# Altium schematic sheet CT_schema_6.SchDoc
size 405 x 220 mm
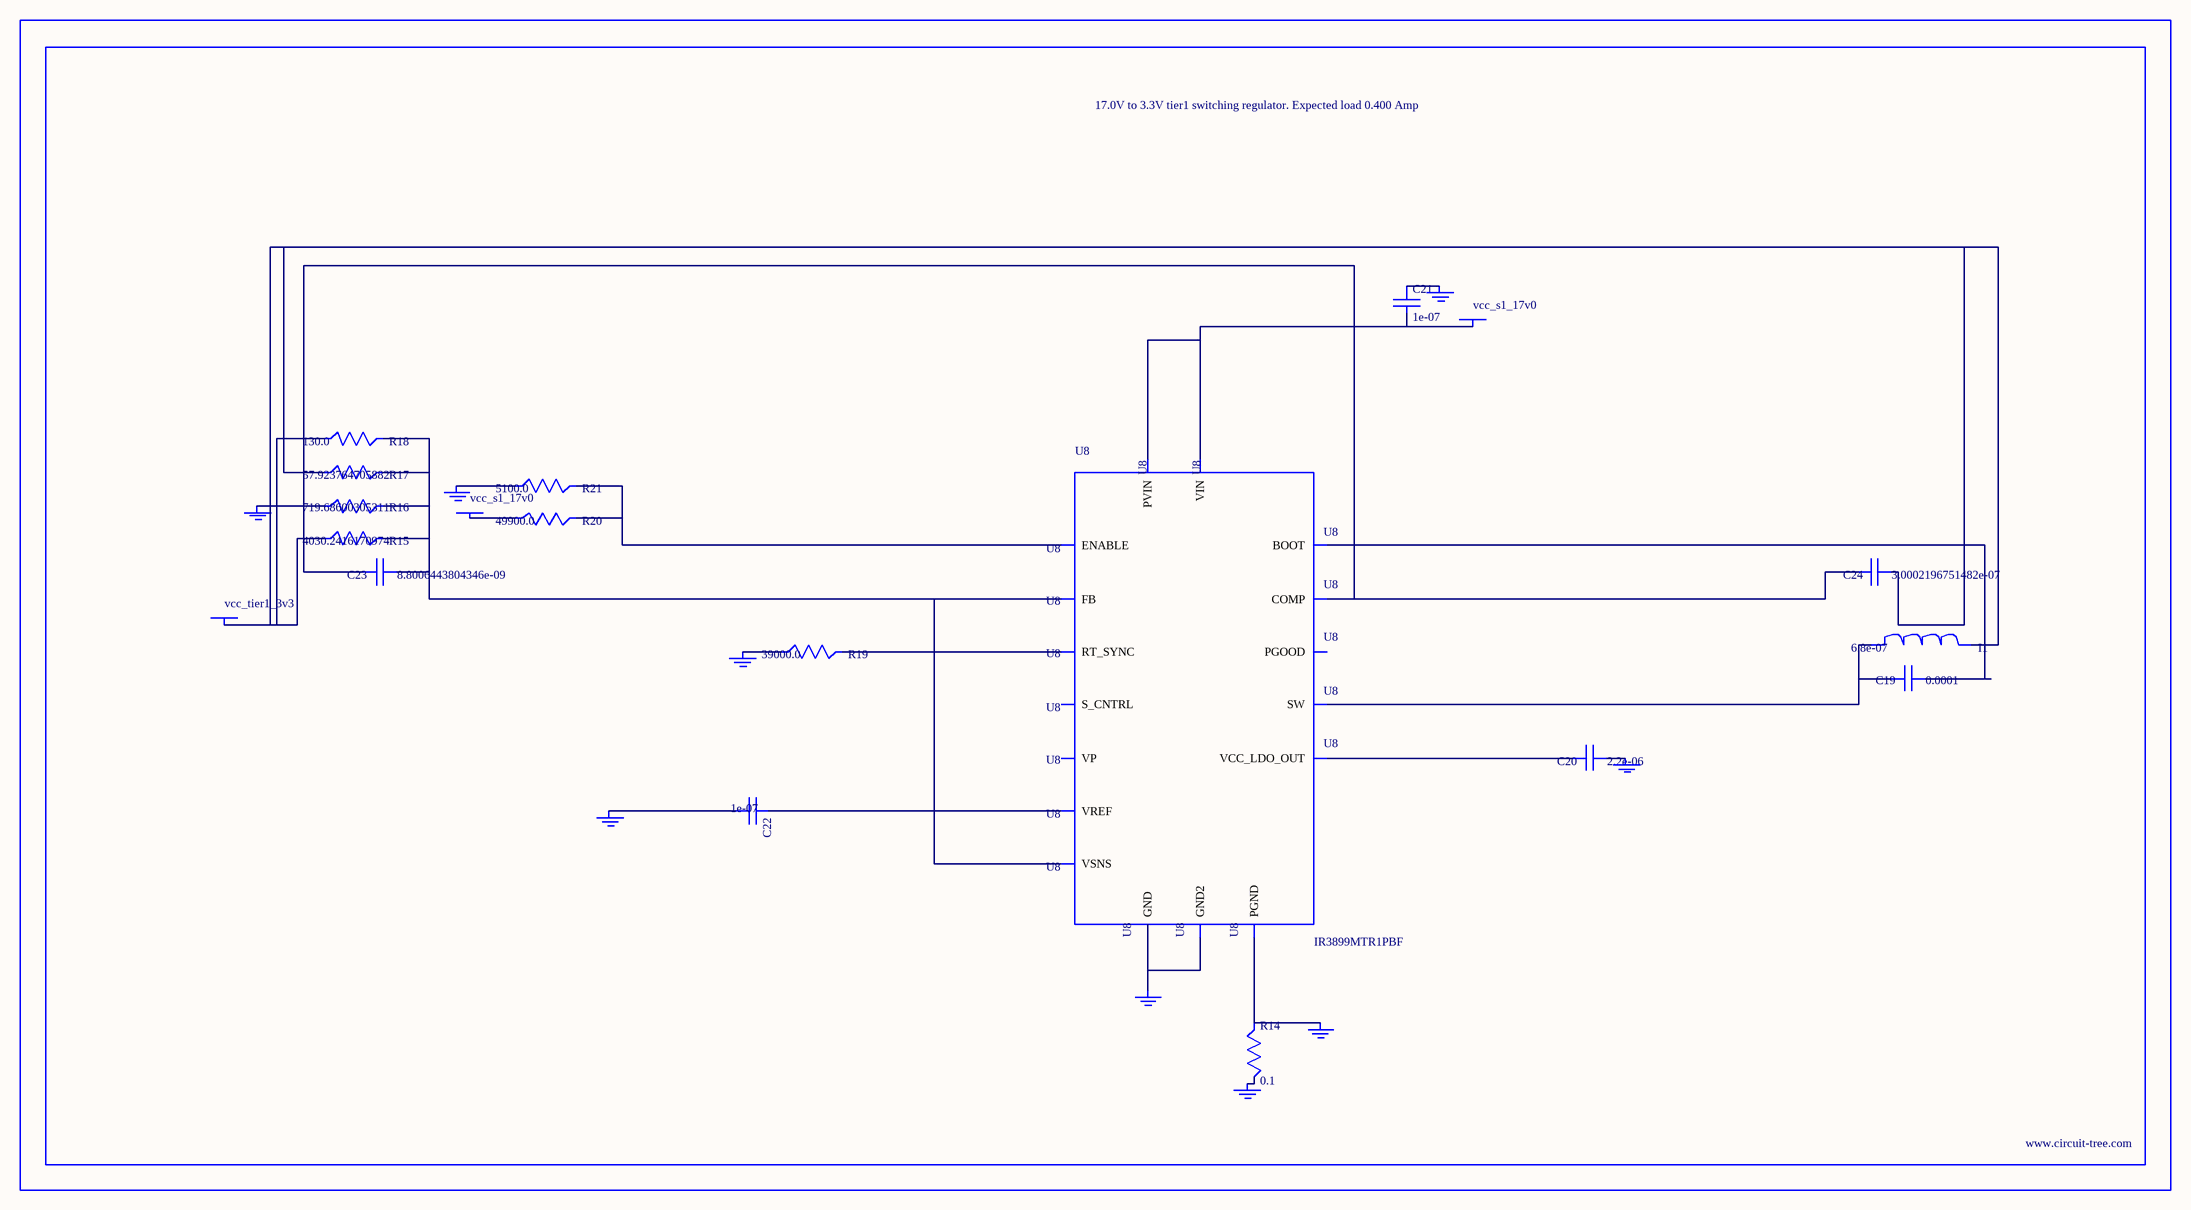
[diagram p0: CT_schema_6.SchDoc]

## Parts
BORDER5  (no value)
C19  0.0001  [C1210]
C20  2.2e-06  [C0603]
C21  1e-07  [C0402]
C22  1e-07  [C0402]
C23  8.8006443804346e-09  [R0603]
C24  3.0002196751482e-07  [R0603]
GND_INSTANCE_5_0  (no value)
GND_INSTANCE_5_1  (no value)
GND_INSTANCE_5_2  (no value)
GND_INSTANCE_5_3  (no value)
GND_INSTANCE_5_4  (no value)
GND_INSTANCE_5_5  (no value)
GND_INSTANCE_5_6  (no value)
GND_INSTANCE_5_7  (no value)
GND_INSTANCE_5_8  (no value)
I1  6.8e-07  [IND25X25CZ]
POWER_INSTANCE_5_0  vcc_s1_17v0
POWER_INSTANCE_5_1  vcc_s1_17v0
POWER_INSTANCE_5_2  vcc_tier1_3v3
R14  0.1  [R0603]
R15  4030.2416170974  [R0603]
R16  719.68600305311  [R0603]
R17  57.923764705882  [R0603]
R18  130.0  [R0603]
R19  39000.0  [R0603]
R20  49900.0  [R0603]
R21  5100.0  [R0603]
U8  IR3899MTR1PBF  [IR3899MTR1PBF]

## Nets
NetC19_1: C19.1 U8.14(BOOT)
NetC19_2: C19.2 I1.1 U8.12(SW)
NetC20_1: C20.1 GND_INSTANCE_5_4.0(GND)
NetC20_2: C20.2 U8.10(VCC_LDO_OUT)
NetC21_1: C21.1 GND_INSTANCE_5_3.0(GND)
NetC21_2: C21.2 POWER_INSTANCE_5_0.0(PWR) U8.9(VIN) U8.13(PVIN)
NetC22_1: C22.1 U8.2(VREF)
NetC22_2: C22.2 GND_INSTANCE_5_1.0(GND)
NetC23_1: C23.1 R15.2 R16.2 R17.2 R18.2 U8.1(FB) U8.8(VSNS)
NetC23_2: C23.2 C24.2 U8.3(COMP)
NetC24_1: C24.1 I1.2 POWER_INSTANCE_5_2.0(PWR) R15.1 R17.1 R18.1
NetGND_INSTANCE_5_0_0: GND_INSTANCE_5_0.0(GND) R16.1
NetGND_INSTANCE_5_2_0: GND_INSTANCE_5_2.0(GND) R19.1
NetGND_INSTANCE_5_5_0: GND_INSTANCE_5_5.0(GND) R14.2
NetGND_INSTANCE_5_6_0: GND_INSTANCE_5_6.0(GND) R14.1 U8.11(PGND)
NetGND_INSTANCE_5_7_0: GND_INSTANCE_5_7.0(GND) R21.1
NetGND_INSTANCE_5_8_0: GND_INSTANCE_5_8.0(GND) U8.4(GND) U8.17(GND2)
NetPOWER_INSTANCE_5_1_0: POWER_INSTANCE_5_1.0(PWR) R20.1
NetR19_2: R19.2 U8.5(RT_SYNC)
NetR20_2: R20.2 R21.2 U8.15(ENABLE)

Not connected (* = marked no-connect by the designer): U8 6(S_CNTRL) 7(PGOOD) 16(VP)

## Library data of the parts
BORDER5 = BORDER_PAGE5
C19 = GRM32ER61A107ME20L
C20 = C0603C225K8RACTU
C21 C22 = C0402C104K3RACTU
C23 = C23
C24 = C24
GND_INSTANCE_5_0-GND_INSTANCE_5_8 = GND
I1 = IHLP2525CZERR68M01
POWER_INSTANCE_5_0-POWER_INSTANCE_5_2 = PWR
R14 = ERJ-3RSFR10V
R15 = R15
R16 = R16
R17 = R17
R18 = RC0603JR-07130RL
R19 = RC0603JR-0739KL
R20 = RC0603FR-0749K9
R21 = RC0603JR-075K1L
